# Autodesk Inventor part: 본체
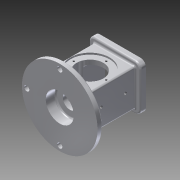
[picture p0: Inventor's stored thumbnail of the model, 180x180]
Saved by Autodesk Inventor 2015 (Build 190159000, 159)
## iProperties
Created: 2019-08
Part Number: 본체
Material: 알루미늄 6061
Document SubType Name: Modeling
Designer: a5
Density: 2.7 g/cm^3
Appearance: 알루미늄 - 평지
Mass: 1041.45 g
Surface Area: 783.684 cm^2
Volume: 385.722 cm^3
Author: a5
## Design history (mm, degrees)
sketch "스케치1"
  geometry: L1 (37, -33)-(-37, -33); L2 (-37, -33)-(-37, 33); L3 (-37, 33)-(37, 33); L4 (37, 33)-(37, -33); 3 further points
  constraints: 8 end point, 2 midpoint, 2 parallel, 1 horizontal, 1 horizontal alignment, 1 perpendicular, 1 vertical alignment
  dimensions: "d0" = 74 distance of L2.end L3.end; "d1" = 66 distance of L1.end L2.end
extrude "돌출1" new body sketch "스케치1" stored distance "d2" = 108; taper "d3" = 0 deg
sketch "스케치2"
  geometry: C1 r 67.5 at (0, 0); C2 r 4.5 at (0, 59); C3 r 4.5 at (0, -59); C4 r 4.5 at (-59, 0); 1 further point
  constraints: 4 centre point, 2 vertical alignment, 1 coincident, 1 horizontal alignment
  dimensions: "d4" = 67.5 radius of C1; "d5" = 4.5 radius of C2; "d6" = 4.5 radius of C3; "d7" = 4.5 radius of C4; "d8" = 118 distance of C3.centre C2.centre; "d9" = 59 distance of point (0, 0) C2.centre; "d10" = 59 distance of C4.centre point (0, 0)
extrude "돌출2" join sketch "스케치2" distance "d11" = 10; taper "d12" = 0 deg
sketch "스케치3"
  geometry: L1 (-46, -41)-(46, -41); L2 (46, -41)-(46, 41); L3 (46, 41)-(-46, 41); L4 (-46, 41)-(-46, -41); 3 further points
  constraints: 8 end point, 2 midpoint, 2 parallel, 1 horizontal, 1 horizontal alignment, 1 perpendicular, 1 vertical alignment
  dimensions: "d13" = 92 distance of L3.end L2.end; "d14" = 82 distance of L2.end L1.end
extrude "돌출3" join sketch "스케치3" distance "d15" = 10; taper "d16" = 0 deg
sketch "스케치4"
  geometry: C1 r 35 at (37, 44); 1 further point
  constraints: 1 centre point, 1 coincident
  dimensions: "d17" = 35 radius of C1
extrude "돌출4" cut sketch "스케치4" distance "d18" = 3; taper "d19" = 0 deg
sketch "스케치5"
  geometry: C1 r 24 at (0, 0); 1 further point
  constraints: 1 centre point, 1 coincident
  dimensions: "d20" = 24 radius of C1
extrude "돌출5" cut sketch "스케치5" distance "d21" = 40; taper "d22" = 0 deg
sketch "스케치7"
  geometry: L1 (-26, -26)-(26, -26); L2 (26, -26)-(26, 26); L3 (26, 26)-(-26, 26); L4 (-26, 26)-(-26, -26); 3 further points
  constraints: 8 end point, 2 midpoint, 2 parallel, 1 horizontal, 1 horizontal alignment, 1 perpendicular, 1 vertical alignment
  dimensions: "d34" = 52 distance of L3.end L2.end; "d35" = 52 distance of L2.end L1.end
extrude "돌출6" cut sketch "스케치7" distance "d36" = 8; taper "d37" = 0 deg
sketch "스케치8"
  geometry: L1 (-22, -22)-(22, -22); L2 (22, -22)-(22, 22); L3 (22, 22)-(-22, 22); L4 (-22, 22)-(-22, -22); 3 further points
  constraints: 8 end point, 2 midpoint, 2 parallel, 1 horizontal, 1 horizontal alignment, 1 perpendicular, 1 vertical alignment
  dimensions: "d38" = 44 distance of L3.end L2.end; "d39" = 44 distance of L2.end L1.end
extrude "돌출7" cut sketch "스케치8" distance "d40" = 74; taper "d41" = 0 deg
sketch "스케치9"
  geometry: C1 r 25 at (0, 0); 1 further point
  constraints: 1 centre point, 1 coincident
  dimensions: "d42" = 25 radius of C1
extrude "돌출8" cut sketch "스케치9" distance "d43" = 18; taper "d44" = 0 deg
sketch "스케치10"
  geometry: C1 r 12.5 at (0, 0); 1 further point
  constraints: 1 centre point, 1 coincident
  dimensions: "d45" = 12.5 radius of C1
extrude "돌출9" cut sketch "스케치10" stored distance "d46" = 18; taper "d47" = 0 deg
sketch "스케치11"
  geometry: L1 (100.5, -10)-(-34.5, -10) reference; 3 further points
  constraints: 2 vertical alignment
  dimensions: "d48" = 37 distance from line of L1 point (33, 27); "d49" = 43 distance of point (33, 70) point (33, 27)
hole "구멍2" sketch "스케치11" at (33, 70), (33, 27) diameter "d50" = 4.917; stored, may be unused: countersink angle "d54" = 90 deg, drill point angle "d56" = 118 deg; dims "d51" = 30, "d52" = 4, "d53" = 2, "d55" = 30
sketch "스케치12"
  geometry: C1 r 59 at (0, 0); 1 further point
  constraints: 1 centre point, 1 coincident, 1 other
  dimensions: "d57" = 59 radius of C1
feature "엠보싱1" sketch "스케치12" dims "d0" = 74, "d1" = 66, "d13" = 92, "d14" = 82, "d58" = 0.5, "d59" = 0
chamfer "모따기1" distance "d60" = 3; stored, may be unused: second distance "d61" = 2, angle "d62" = 45 deg
fillet "모깎기1" dims "d63" = 3
fillet "모깎기2" dims "d64" = 3
fillet "모깎기3" dims "d65" = 10
fillet "모깎기4" dims "d66" = 3
chamfer "모따기2" distance "d67" = 1; stored, may be unused: second distance "d68" = 2, angle "d69" = 45 deg
fillet "모깎기5" dims "d70" = 3
fillet "모깎기6" dims "d71" = 3
sketch "스케치6"
  geometry: 5 further points
  constraints: 2 horizontal alignment, 2 vertical alignment
  dimensions: "d23" = 29 distance of point (0, 0) point (0, 29); "d86" = 29 distance of point (0, 0) point (-29, 0); "d87" = 58 distance of point (0, -29) point (0, 29); "d88" = 58 distance of point (-29, 0) point (29, 0)
hole "구멍5" sketch "스케치6" at (0, 29), (0, -29), (-29, 0), (29, 0) diameter "d89" = 3.242; stored, may be unused: countersink angle "d93" = 90 deg, drill point angle "d95" = 118 deg; dims "d90" = 4, "d91" = 4, "d92" = 2, "d94" = 6
sketch "스케치13"
  geometry: L1 (36, 41)-(-36, 41) reference; L2 (-46, 31)-(-46, -31) reference; L3 (-36, -41)-(36, -41) reference; L4 (46, -31)-(46, 31) reference; L5 (27, -27)-(27, 27) reference; L6 (-27, -27)-(27, -27) reference; L7 (-27, 27)-(-27, -27) reference; L8 (27, 27)-(-27, 27) reference; A1 r 10 centre (36, 31) between (46, 31) and (36, 41) reference; A2 r 10 centre (-36, 31) between (-36, 41) and (-46, 31) reference; A3 r 10 centre (-36, -31) between (-46, -31) and (-36, -41) reference; A4 r 10 centre (36, -31) between (36, -41) and (46, -31) reference; 5 further points
  constraints: 4 coincident
hole "구멍6" sketch "스케치13" at (-36, -31), (36, -31), (36, 31), (-36, 31) diameter "d96" = 3.242; stored, may be unused: countersink angle "d100" = 90 deg, drill point angle "d102" = 118 deg; dims "d97" = 4, "d98" = 4, "d99" = 2, "d101" = 6
node "솔리드1"
mirror "대칭2"
node "투영된 루프1"
